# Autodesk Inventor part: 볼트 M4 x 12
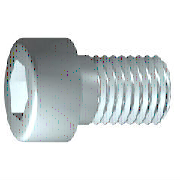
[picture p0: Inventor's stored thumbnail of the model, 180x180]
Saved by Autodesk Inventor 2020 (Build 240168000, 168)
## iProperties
IsCustomPart: 0
Created: 2012-02
Part Number: 볼트 M4 x 12
Material: 강철, 연강
Description: 6각 소켓 머리 캡 나사
Document SubType Name: Modeling
Standard: ISO 4762
Designer: mduedu
Standard Revision: Fourth edition 2004-03-01
Standards Organization: ISO
Language: ko-KR
Size Designation: M4 x 12
Categories: <MemberInstance><Categories><Category DisplayName="조임쇠" InternalName="e4da775c-781d-43d5-af7c-5136215cf5a6" Mnemonic="FSTN"><Category DisplayName="볼트" InternalN
Density: 7.86 g/cm^3
Mass: 2.23465 g
Surface Area: 3.30853 cm^2
Volume: 0.284306 cm^3
Appearance: 강철
Author: mduedu
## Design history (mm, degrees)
sketch "스케치1"
  geometry: L1 (-1, 0)-(12, 0); L2 (12, 0)-(12, 2); L3 (12, 2)-(1.75, 2); L4 (1.75, 2)-(1.32, 2); L5 (1.32, 2)-(0, 2); L6 (0, 2)-(0, 3.5); L7 (0, 3.5)-(-4, 3.5); L8 (-4, 3.5)-(-4, 1.732); L9 (-4, 1.732)-(-2, 1.732); L10 (-2, 1.732)-(-1, 0); L11 (-7.2, 0)-(15.2, 0) reference; L12 (0, -0.7)-(0, 4.2) reference; L13 (1.75, 2)-(0, 2)
  constraints: 22 end point, 6 parallel, 2 collinear, 2 perpendicular, 1 horizontal, 1 point on line
  dimensions: "d1" = 10.25 distance from line of L3.end L2 (= GEL); "d2" = 0.42952 distance of L4.end L3.end (computed from GAL); "d3" = 4 distance between parallel lines of L8 L6 (= KOH); "d4" = 2 distance of L8.end L9.end (= INTI); "d5" = 60 deg angle of L10 L1; "d6" = 4 diameter of L3 L1 (= GD); "d7" = 4 diameter of L5 L1 (= BDM); "d8" = 3.4641 diameter of L9 L1 (= 1.1547 x SW); "d9" = 7 diameter of L7 L1 (= KOD); "d26" = 12 distance between parallel lines of L12 L2 (= NLG)
revolve "본체" sketch "스케치1" stored, may be unused: angle "d10" = 90 deg
sketch "스케치2"
  geometry: L1 (0, -4.9)-(0, 4.9) reference; L2 (-4.9, 0)-(4.9, 0) reference; L3 (1.732, 0)-(0.866, -1.5); L4 (0.866, -1.5)-(-0.866, -1.5); L5 (-0.866, -1.5)-(-1.732, 0); L6 (-1.732, 0)-(-0.866, 1.5); L7 (-0.866, 1.5)-(0.866, 1.5); L8 (0.866, 1.5)-(1.732, 0); 2 further points
  constraints: 12 end point, 1 coincident, 1 horizontal alignment, 1 point on line, 12 other
extrude "슬롯" join sketch "스케치2" stored distance "d11" = 10; taper "d12" = 0 deg
workplane "Work Plane1"
fillet "Fillet2" dims "d30" = 0.1 (= R)
body "Solid1"
fillet "모깎기1" dims "d17" = 0.4 (= RR)
feature "스레드" dims "d13" = 10.25 (= GEL), "d14" = 0
chamfer "모따기1" distance "d15" = 0.42941 (= -0.5 x SPD + 0.5 x GD); stored, may be unused: second distance "d16" = 0.42941 (= GUL), angle "d27" = 45 deg
other parameters: "GD" = 4 [user parameter; used in 2 equation terms], "NLG" = 12 [user parameter; used in 1 equation term], "GEL" = 10.25 [user parameter; used in 2 equation terms], "KOD" = 7 [user parameter; used in 1 equation term], "KOH" = 4 [user parameter; used in 1 equation term], "INTI" = 2 [user parameter; used in 1 equation term], "GAL" = 0.42941 (= 0.61345 x PTC) [user parameter; used in 1 equation term], "GUL" = 0.42941 (= 0.61345 x PTC) [user parameter; used in 1 equation term], "BDM" = 4 (= NND) [user parameter; used in 1 equation term], "SW" = 3 [user parameter; used in 2 equation terms], "RR" = 0.4 [user parameter; used in 1 equation term], "SPD" = 3.14117 (= NND - 1.2269 x PTC) [user parameter; used in 1 equation term], "d19" = 0, "d28" = 0, "d29" = 0, "R" = 0.1 [user parameter; used in 1 equation term], "TOA" = 30 deg [user parameter], "GD1" = 3.14117 (= THREADDIA - 1.2269 x PTC) [user parameter], "THREADDIA" = 4 [user parameter; used in 1 equation term], "FAWI" = 45 deg [user parameter], "TPU" = 14.28571 (computed from PTC) [user parameter], "PTC" = 0.7 [user parameter; used in 5 equation terms], "NND" = 4 [user parameter; used in 2 equation terms], "E0" = 3.465 (= 1.155 x SW) [user parameter]
